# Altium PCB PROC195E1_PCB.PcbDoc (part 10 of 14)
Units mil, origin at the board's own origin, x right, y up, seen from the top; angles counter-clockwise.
Board outline 3110.24 x 2500 mil, 10 copper layers (Top Layer, L02_GND1, L03_SIG1, L04_GND2, L05_PWR1, L06_PWR2, L07_GND3, L08_SIG2, L09_GND4, Bottom Layer), stack 66.407 mil thick; 571 components, 538 nets, 6726 pads, 1286 vias.
Unrouted connection lines stored in the file: 4.
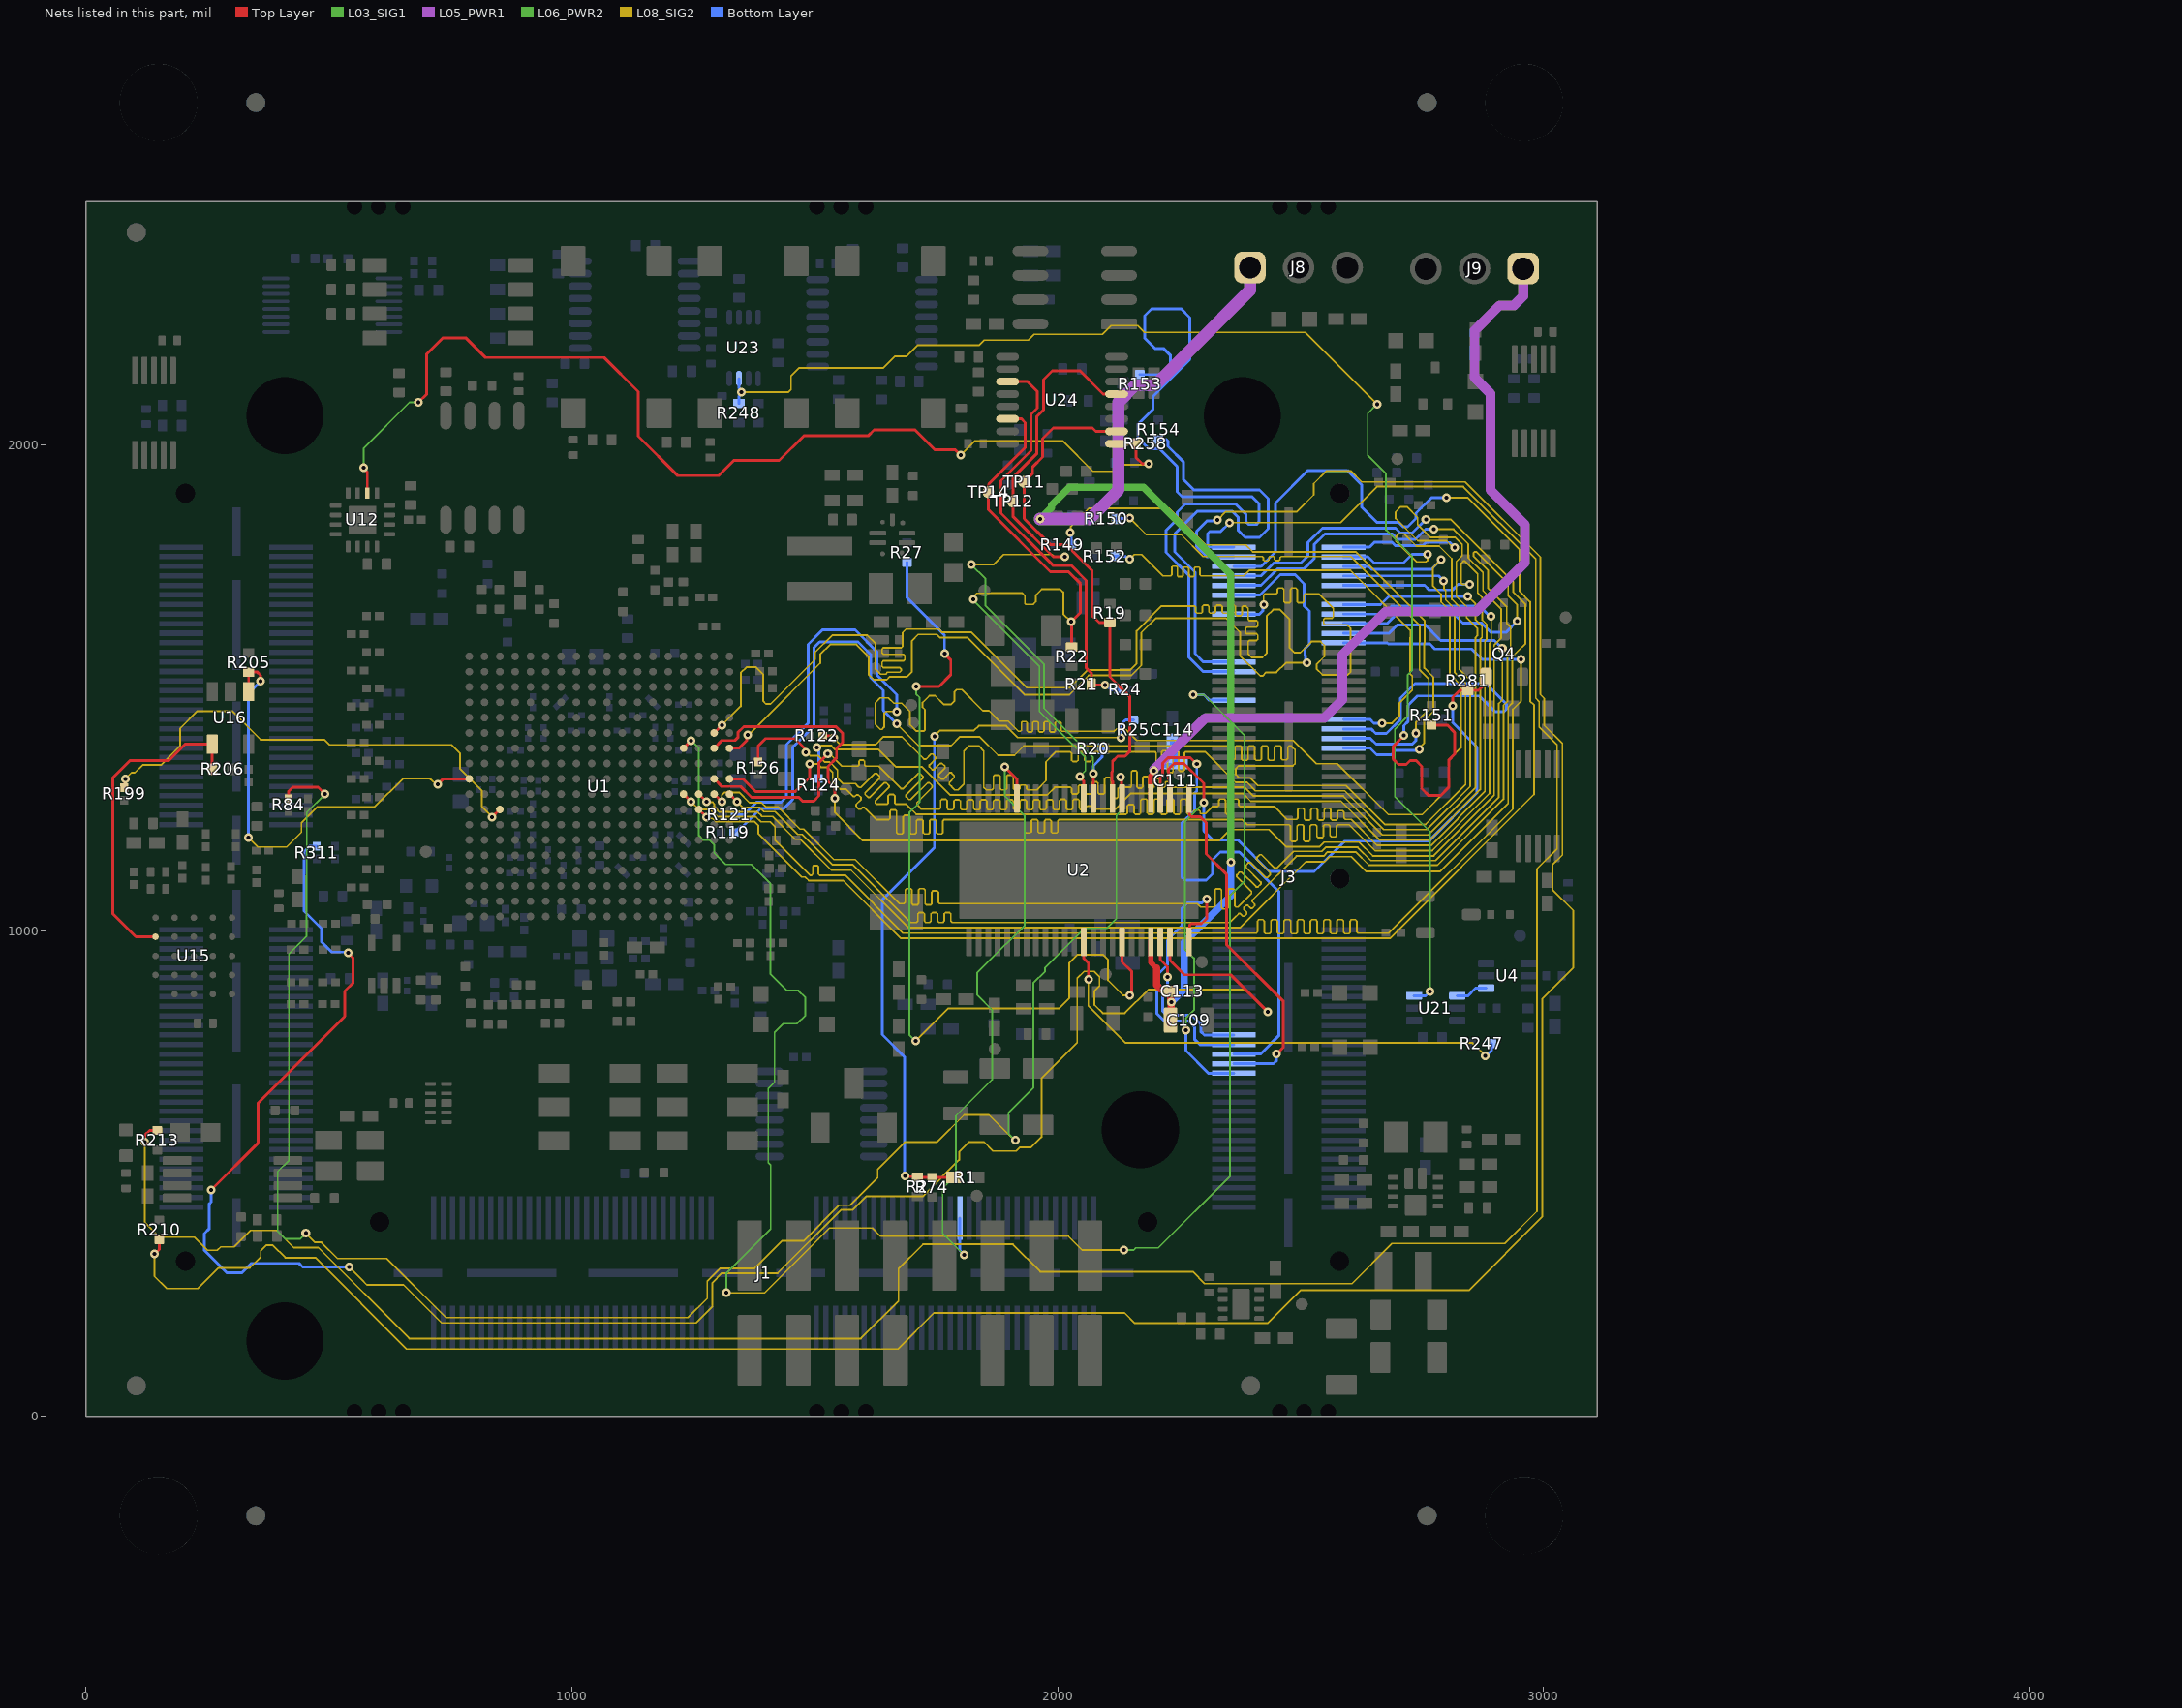
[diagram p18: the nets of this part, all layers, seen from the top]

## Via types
v1: diameter 18, hole 8, Top Layer to Bottom Layer, tented both sides, 1226 vias
v2: diameter 19.68, hole 7.87, Top Layer to Bottom Layer, tented top, 54 vias
v3: diameter 19.68, hole 7.87, Top Layer to Bottom Layer, 4 vias
v4: diameter 19.68, hole 7.87, Top Layer to Bottom Layer, tented both sides, 2 vias

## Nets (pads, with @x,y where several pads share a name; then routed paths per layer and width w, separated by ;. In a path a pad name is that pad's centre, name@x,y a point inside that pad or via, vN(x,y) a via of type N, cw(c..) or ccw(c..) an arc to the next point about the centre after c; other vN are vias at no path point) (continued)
OSPI0_LBCLK: R199.2 U1.L3 | length 1003.3
  Top Layer w5.8: R199.2@79.05,1294.4 80.37,1295.72 80.37,1311.13 v1(81.69,1312.45) ; v1(836.41,1233.76) U1.L3@852.13,1249.45
  L08_SIG2 w3.6: v1(81.69,1312.45) 94.26,1325.02 101.06,1325.02 116.84,1340.8 154.71,1340.8 194.27,1380.36 194.27,1416.24 229.73,1451.7 301,1451.7 359.61,1393.09 490.68,1393.09 501.3,1382.47 752.9,1382.47 770.02,1365.35 770.02,1333.28 815.33,1287.97 815.33,1254.84 v1(836.41,1233.76)
OSPI0_RESET_OUTn: R205.1 U1.J1 U16.1 | length 953.6
  Top Layer w5.8: U16.1@335.2,1491.94 R205.1@335.2,1531.94 353.14,1531.94 359.9,1525.19 359.9,1513.68 v1(360.01,1513.57) ; v1(724.08,1301.38) 724.68,1301.38 735.74,1312.44 771.03,1312.44 U1.J1@789.16,1312.44
  L08_SIG2 w3.6: v1(334.47,1191.98) 354.53,1171.92 413.48,1171.92 444,1202.44 444,1222 476.45,1254.45 594.28,1254.45 652.78,1312.96 707.98,1312.96 710.06,1310.88 711.04,1310.88 720.46,1301.46 720.54,1301.38 v1(724.08,1301.38)
  Bottom Layer w5.8: v1(334.47,1191.98) 334.47,1488.03 v1(360.01,1513.57)
OSPI0_RST#: R206.1 U15.A4 U16.4 | length 672.8
  Top Layer w5.8: U15.A4@143.59,987.35 103.2,987.35 55.36,1035.19 55.36,1314.09 91.59,1350.32 171.28,1350.32 204.64,1383.67 U16.4@260.39,1383.67 260.39,1333.05 R206.1@261.38,1332.07
PHY0_25MHZ_CLK: J3.117 R210.2 | length 5601
  Top Layer w5.8: v1(141.5,335) 142.36,335 151.15,343.78 R210.2@151.15,363.92
  L08_SIG2 w3.6: v1(141.5,335) 141.5,288.28 166.44,263.34 230.81,263.34 273.33,305.86 337.7,305.86 360.03,328.2 360.03,340.98 371.27,352.22 385.14,352.22 410.68,326.68 472.38,326.68 660.33,138.73 1265.59,138.73 1265.66,138.79 1671.15,138.79 1745.41,213.05 2137.55,213.05 2158.72,191.88 2431.91,191.88 2499.65,259.62 2846.1,259.62 2997.12,410.64 2997.12,859.28 3061.41,923.57 3061.41,1041.1 3018.06,1084.45 3018.06,1135.24 3038.5,1155.68 3038.5,1384.97 3001.35,1422.12 3001.35,1477.99 2993.41,1485.92 2993.41,1768.67 2838.78,1923.31 2625.69,1923.31 2603,1946 2553,1946 2527,1920 2527,1897 2492.43,1862.43 2346.49,1862.43 v1(2328.93,1844.87)
  Bottom Layer w5.8: v1(2328.93,1844.87) 2327.59,1843.54 2307.95,1843.54 2286.13,1821.72 2286.13,1790.02 2306.85,1769.31 J3.117@2362.43,1769.31
PHY1_25MHZ_CLK: J3.119 R213.2 | length 5655.9
  Top Layer w5.8: v1(121.78,564.83) 121.78,579.08 131.39,588.69 R213.2@147.24,588.69
  L08_SIG2 w3.6: v1(121.78,564.83) 121.78,398.63 151.57,368.84 223.72,368.84 250.64,341.92 270.88,341.92 277.91,348.96 305.01,348.96 339,382.95 392.57,382.95 427.96,347.57 478.64,347.57 665.88,160.33 1595.06,160.33 1672.55,237.82 1672.55,304 1722.88,354.34 1907.9,354.34 1964.27,297.97 2278.14,297.97 2302.66,273.44 2605.65,273.44 2688.32,356.12 2920.19,356.12 2986.32,422.25 2986.32,1126.89 3027.7,1168.26 3027.7,1382.2 2990.92,1418.97 2990.92,1471.38 2983.81,1478.48 2983.81,1764.69 2834.8,1913.71 2656.69,1913.71 2582.56,1839.58 v1(2353.36,1839.58)
  Bottom Layer w5.8: v1(2353.36,1839.58) 2353.36,1839.08 2335.33,1821.05 2312.92,1821.05 2309,1817.13 2309,1792.02 2311.87,1789.15 J3.119@2362.59,1789.15
PLDO1_OUT: C109.1 C113.1 J8.1 U2.20 | length 2391.8
  Top Layer w11: U2.20@2191.65,976.67 2191.65,934.71 2203.54,922.83
  Top Layer w15: 2203.54,922.82 2203.54,888.02 2212.33,879.23 2227.07,879.23 C113.1@2231.91,874.39 ; C109.1@2232.44,815.79 2233.27,816.63 2233.27,851.83 v1(2233.85,852.41) ; v1@2232.44,854.99 C113.1@2232.44,874.92
  L05_PWR1 w25: v1(1963.58,1847.2) 2065.28,1847.2 2125.34,1907.26 2125.34,2087.76 2160.58,2123 2201.16,2123 2278.66,2200.49 2278.66,2200.88 2395.83,2318.06 J8.1@2395.83,2364.93
  L06_PWR2 w15: v1(1963.58,1847.2) 1987.4,1871.01 1987.4,1875.32 2024.43,1912.35 2177.02,1912.35 2356.19,1733.17 v1(2356.19,1141.18)
  Bottom Layer w15: v1@2234.42,852.98 2260.24,878.8 2260.24,975.86 2356.19,1071.82 v1(2356.19,1141.18)
PLDO2_OUT: C111.1 C114.1 J9.1 U2.29 | length 1861.4
  Top Layer w10: U2.29@2191.65,1271.95 2191.65,1319.55 2195.1,1323 2195.1,1324.21 2198.24,1327.35 v1(2198.24,1329.51)
  L05_PWR1 w20: v1(2198.24,1329.51) 2198.24,1331.86 2304.44,1438.06 2549.06,1438.06 2586,1475 2586,1568 2675.07,1657.07 2861.31,1657.07 2961.89,1757.65 2961.89,1835.24 2890.27,1906.87 2890.27,2105.73 2858.11,2137.89 2858.11,2235.4 2909.68,2286.97 2939.05,2286.97 2957.95,2305.87 J9.1@2957.95,2362.59
  Bottom Layer w10: v1(2198.24,1329.51) 2198.46,1329.51 2208.96,1340.02 2236.25,1340.02 C111.1@2242.33,1346.1 ; C114.1@2235.75,1389.54 2235.75,1370.3 2241.61,1364.44 2241.61,1346.82 C111.1@2242.77,1345.66
PMIC_COMP1_IN+: J3.37 U2.21 | length 328.7
  Top Layer w5.8: U2.21@2211.34,976.67 2211.34,940.32 2226.05,925.6 v1@2226.05,904.23
  Bottom Layer w5.8: v1(2226.04,904.21) 2226.04,884.52 2215.95,874.43 2215.95,834.22 2223.93,826.24 2275.77,826.24 2295.15,806.86 2295.15,791.46 2301.51,785.1 J3.37@2362.59,785.1
PMIC_COMP1_IN-: J3.35 U2.24 | length 612.7
  Top Layer w5.8: U2.24@2270.39,976.67 2271.44,977.72 2271.44,1010.62 2274.84,1014.02 2296.1,1014.02 2306.7,1024.62 v1(2306.7,1065.31)
  Bottom Layer w5.8: v1(2306.7,1065.31) 2305.08,1065.31 2296.68,1056.91 2267.18,1056.91 2255.6,1045.33 2255.6,1009.89 2226.2,980.49 2226.2,929.68 2204.15,907.63 2204.15,829.33 2219.04,814.44 2269.19,814.44 2281.55,802.07 2281.55,776.56 2292.69,765.41 J3.35@2362.59,765.41
PMIC_COMP2_IN+: J3.33 U2.28 | length 1082.5
  Top Layer w5.8: U2.28@2211.34,1271.95 2210.87,1272.41 2210.87,1315.62 2216.14,1320.89 2216.14,1345.08 2226.85,1355.78 2273.13,1355.78 v1(2286.34,1342.57)
  Bottom Layer w5.8: v1(2286.34,1342.57) 2286.28,1342.51 2286.28,1287.3 2281.78,1282.8 2281.78,1247.14 2255.6,1220.96 2255.6,1110.46 2262.36,1103.7 2305.77,1103.7 2318.6,1116.53 2318.6,1145.81 2334.52,1161.73 2373.89,1161.73 2454.91,1080.71 2454.91,783.48 2417.16,745.73 J3.33@2362.59,745.73
PMIC_COMP2_IN-: J3.31 U2.25 | length 727.1
  Top Layer w5.8: U2.25@2270.39,1271.95 2271.44,1270.9 2271.44,1238 2274.84,1234.6 2293,1234.6 2293.39,1234.22 2293.46,1234.22 2305.65,1222.03 2305.65,1157.76 2347.28,1116.13 2347.28,971.51 2464.52,854.27 2464.52,760.21 v1(2450.71,746.4)
  Bottom Layer w5.8: J3.31@2362.59,726.04 2444.28,726.04 2450.71,732.48 v1(2450.71,746.4)
PMIC_DIAG_OUT: R84.2 U2.32 | length 3788.9
  Top Layer w5.8: R84.2@417.42,1271.47 417.42,1286.62 425.76,1294.97 478.38,1294.97 v1(492.49,1280.86) ; v1(2129.37,1316.27) 2130.98,1314.65 2130.98,1273.56 U2.32@2132.6,1271.95
  L03_SIG1 w3.6: v1(452.85,377.2) 440.84,365.19 411.04,365.19 395.11,381.12 395.11,504.05 417.84,526.78 417.84,952.31 454.6,989.07 454.6,1114.06 454.99,1114.46 454.99,1243.35 v1@492.49,1280.84 ; v1(1912.95,568.37) 1898.89,582.43 1898.89,625.05 1949.84,676.01 1949.84,891.8 1974.21,916.17 1974.21,923.65 2055.15,1004.6 2101.08,1004.6 2120.86,1024.38 2120.86,1062.66 2120.86,1236.86 2130.92,1246.92 2130.92,1314.71 v1(2129.37,1316.27)
  L08_SIG2 w3.6: v1(452.85,377.2) 471.69,358.37 484.99,358.37 518.09,325.27 619.57,325.27 741.32,203.53 1239.31,203.53 1278.75,242.96 1278.75,277.99 1305.23,304.47 1375.69,304.47 1432.62,361.39 1476.82,361.39 1550.14,434.72 1572.52,434.72 1629.48,491.69 1629.48,508.83 1685.25,564.59 1751.57,564.59 1807.54,620.55 1859.03,620.55 1911.22,568.37 v1(1912.95,568.37)
PMIC_EN_OUT: R27.1 U2.17 | length 1832.8
  Top Layer w5.8: v1(1708.6,1502.72) 1756.1,1502.72 1780.17,1526.79 1780.17,1556.82 v1(1767.22,1569.77) ; U2.17@2132.6,976.67 2132.6,935.67 2152.29,915.97 2152.29,874.06 2148.3,870.06 v1(2148.3,866.76)
  L03_SIG1 w3.6: v1(1707.74,772.84) 1694.78,785.81 1694.78,1243.13 1715.8,1264.15 1715.8,1479.7 1708.6,1486.9 v1(1708.6,1502.72)
  L08_SIG2 w3.6: v1(1707.74,772.84) 1774.9,840 2003.46,840 2023.61,860.15 2023.61,932.56 2041.61,950.56 2092.89,950.56 2103.72,939.73 2103.72,897.6 2134.55,866.76 v1(2148.3,866.76)
  Bottom Layer w5.8: R27.1@1689.83,1757.96 1689.83,1685.35 1767.22,1607.96 v1(1767.22,1569.77)
PMIC_INTn: R311.2 U2.22 | length 4209.8
  Top Layer w5.8: v1(257.93,466.28) 355.02,563.37 355.02,645.28 533.2,823.47 533.2,875.5 549.75,892.04 549.75,943.92 v1(539.62,954.06) ; U2.22@2231.02,976.67 2231.02,939.02 2261,909.04 2356.11,909.04 v1(2431.92,833.23)
  L08_SIG2 w3.6: v1(542.23,307.73) 542.23,307.38 567.49,282.13 578.77,270.84 654.16,270.84 732.27,192.73 1256.11,192.73 1289.55,226.16 1289.55,275.21 1309.2,294.87 1423.86,294.87 1554.12,425.12 1578.17,425.12 1605.91,452.86 1722,452.86 1797.33,528.18 1797.33,543.98 1818.23,564.88 1848.38,564.88 1866.9,546.36 1914.71,546.36 1922.27,553.92 1945.69,553.92 1966.74,574.97 1966.74,695.65 2040.3,769.21 2040.3,901.71 2054.68,916.09 2074.7,916.09 2085.94,904.84 2085.94,885.99 2075.75,875.8 2075.75,846.82 2092.65,829.92 2138.26,829.92 2186.79,878.45 2385.84,878.45 2431.07,833.23 v1(2431.92,833.23)
  Bottom Layer w5.8: v1(257.93,466.28) 257.93,441.29 254.41,437.76 254.41,386.74 243.88,376.22 243.88,342.06 289.86,296.09 321.84,296.09 340.88,315.13 438.7,315.13 446.27,307.56 542.06,307.56 v1(542.23,307.73) ; R311.2@475.11,1173.35 460.32,1173.35 449.51,1162.54 449.51,1040.13 485.39,1004.25 485.39,976.78 506.31,955.85 537.82,955.85 v1(539.62,954.06)
PMIC_nRST: R247.1 U2.13 | length 1026.1
  Top Layer w5.8: U2.13@2053.86,976.67 2053.86,942.99 2063.21,933.64 v1(2063.21,899.29)
  L08_SIG2 w3.6: v1(2063.21,899.29) 2063.21,845.64 2140.04,768.81 2853.65,768.81 v1(2880.16,742.3)
  Bottom Layer w5.8: v1(2880.16,742.3) 2881.81,742.3 2892.88,753.37 R247.1@2892.88,767.51
PMIC_SAFE_OUT1: R1.1 R2.2 R25.2 R74.2 | length 1529.6
  Top Layer w5.8: v1(1685.66,495) 1687.19,493.47 1709.94,493.47 R2.2@1711.47,491.94 R74.2@1741.47,491.94 R1.1@1786.47,491.94
  L08_SIG2 w3.6: v1(1747.18,1399.72) 1747.18,1400.58 1758.55,1411.96 1828.1,1411.96 1837.7,1421.55 1893.98,1421.55 1905.87,1409.66 1918.04,1397.49 v1@2129.79,1397.49
  Bottom Layer w5.8: v1(1685.66,495) 1685.21,495.46 1685.21,739.6 1638.91,785.9 1638.91,1063.47 1746.29,1170.86 1746.29,1398.84 v1(1747.18,1399.72) ; v1(2130.05,1397.24) 2130.05,1423.7 2139.99,1433.64 R25.2@2155.94,1433.64
PMIC_SAFE_OUT2: J3.29 Q4.1 R281.2 U2.27 | length 1888
  Top Layer w5.8: U2.27@2231.17,1272.09 2231.17,1309.08 2227.94,1312.3 2227.94,1332.41 2239.51,1343.98 2259.62,1343.98 2300.5,1303.1 v1(2300.5,1263.04) ; v1(2812.9,1462.61) 2812.9,1480.31 2826.71,1494.11 2843.59,1494.11 R281.2@2843.82,1494.34 2866.04,1494.34 2874.43,1502.74 2874.43,1515.05 Q4.1@2881.49,1522.1
  L03_SIG1 w3.6: v1(2263.65,794.66) 2264.04,795.05 2264.04,820.03 2280.72,836.71 2280.72,943.22 2261.74,962.2 2261.74,1224.28 v1(2300.5,1263.04)
  Bottom Layer w5.8: v1(2263.65,794.66) 2263.65,753.04 2310.33,706.36 J3.29@2362.59,706.36 ; v1(2300.5,1263.04) 2300.5,1205.15 2319.37,1186.27 2370.94,1186.27 2435.56,1121.66 2528.18,1121.66 2590.52,1184 2763.59,1184 2863,1283.41 2863,1378 2812.9,1428.1 v1(2812.9,1462.61)
PMIC_SPI1/FSIRX0_MUX_SEL: R258.1 U12.2 U24.1 | length 2228.7
  Top Layer w5.8: v1(572.15,1952.84) 572.15,1951.11 579.39,1943.87 U12.2@579.39,1900.61 ; v1(684.78,2087.42) 701.25,2103.9 701.25,2186.66 734.12,2219.54 782.78,2219.54 822.72,2179.6 1066.75,2179.6 1136.93,2109.43 1136.93,2017.51 1218,1936.44 1302.45,1936.44 1333.73,1967.72 1427.07,1967.72 1477.61,2018.25 1609.91,2018.25 1622.36,2030.7 1706.46,2030.7 1747.84,1989.32 1789.8,1989.32 v1(1800.48,1978.63) ; U24.1@2121.29,2002.06 R258.1@2161.29,2002.06 2161.29,1973.44 2173.96,1960.77 v1(2187.23,1960.77)
  L03_SIG1 w3.6: v1(572.15,1952.84) 572.15,1993.18 666.4,2087.42 v1(684.78,2087.42)
  L08_SIG2 w3.6: v1(1800.48,1978.63) 1829.65,2007.8 2010.19,2007.8 2072.61,1945.39 2120.82,1945.39 2134.37,1958.94 2185.4,1958.94 v1(2187.23,1960.77)
PMIC_SPI1_CLK: R19.2 TP11.1 U2.33 U24.2 | length 1066.7
  Top Layer w5.8: TP11.1@1931.18,1923.68 1931.2,1847.84 1984.32,1794.72 2016.86,1794.72 2071.13,1740.46 2071.13,1648.62 2085.58,1634.17 2107,1634.17 R19.2@2107.45,1633.72 2107.45,1522.58 2147.95,1482.09 2147.95,1368.39 2138.73,1359.17 2123.51,1359.17 2113.02,1348.68 2113.02,1327.92 2111.47,1326.37 2111.47,1308.85 2113.1,1307.22 U2.33@2113.1,1272.13 ; TP11.1@1931.18,1923.68 1948.48,1940.98 1948.48,1954.5 1968.94,1974.96 1968.94,2012.7 1991,2034.76 2071.42,2034.76 2078.53,2027.65 U24.2@2121.3,2027.65
PMIC_SPI1_CS0: R22.2 TP14.1 U2.36 U24.14 | length 1458.6
  Top Layer w5.8: TP14.1@1857.69,1902.47 1857.67,1866.22 1985.01,1738.88 2022.21,1738.88 2047,1714.09 2047,1654.93 2028.5,1636.43 v1@2028.5,1635.86 ; TP14.1@1857.69,1902.47 1858.12,1902.9 1858.12,1919.3 1933.05,1994.23 1933.05,2045.72 1925.54,2053.24 U24.14@1896.89,2053.24 ; v1(2028.21,1636.14) 2028.96,1635.4 R22.2@2028.96,1583.68 ; v1(2045.5,1317.37) 2045.5,1316.12 2053.86,1307.75 U2.36@2053.86,1271.95
  L03_SIG1 w3.6: v1(1826.19,1682.21) 1826.19,1680.26 1962.5,1543.95 1962.5,1450.94 2057.19,1356.25 2057.19,1329.06 v1(2045.5,1317.37)
  L08_SIG2 w3.6: v1(1826.19,1682.21) 1826.19,1686.11 1830.44,1690.37 1830.44,1691.12 1833.46,1694.13 1862.95,1694.13 1863.38,1694.56 1911.84,1694.56 1912.26,1694.98 1926.42,1694.98 1932.64,1688.76 1932.64,1673.67 1934.87,1671.45 1949.45,1671.45 1955,1677 1955,1690.52 1967.25,1702.77 2005.31,1702.77 2011.59,1696.5 2011.59,1651.71 2027.16,1636.14 v1(2028.21,1636.14)
PMIC_SPI1_D0: R20.2 TP12.1 U2.35 U24.5 | length 1474.7
  Top Layer w5.8: v1(2015.17,1769.78) 1990.88,1769.78 1907.87,1852.78 TP12.1@1907.87,1883.27 1907.87,1932.28 1956.65,1981.06 1956.65,2057.54 1971,2071.89 1971,2134 1989,2152 2046.35,2152 2093.82,2104.53 U24.5@2121.18,2104.53 ; U2.35@2073.54,1271.95 v1@2073.54,1322.83
  L03_SIG1 w3.6: v1(1822.07,1753.36) 1851.58,1723.84 1851.58,1668.45 1972.1,1547.92 1972.1,1457.26 2073.28,1356.08 v1@2073.28,1322.98
  L08_SIG2 w3.6: v1(1822.07,1753.36) 1868.06,1753.36 1888.8,1774.1 1988.22,1774.1 1992.54,1769.78 v1(2015.17,1769.78)
  Bottom Layer w5.8: v1(2073.39,1322.98) 2073.39,1339.17 2091.58,1357.36 2091.58,1373.28 R20.2@2092.77,1374.47
PMIC_SPI1_D1: R21.2 R24.1 U24.11 | length 862
  Top Layer w5.8: U24.11@1896.89,2130.01 1937.65,2130.01 1957.9,2109.76 1957.9,2075.47 1944.85,2062.43 1944.85,1987.64 1883.29,1926.08 1883.29,1858.98 1990.39,1751.88 2027.6,1751.88 2058.8,1720.68 2058.8,1540.86 2069.21,1530.45 R21.2@2069.21,1507.27 ; R21.2@2069.8,1506.68 2071.33,1505.15 v1(2097.43,1505.15)
  Bottom Layer w5.8: v1(2097.43,1505.15) 2100.54,1505.15 2109.94,1495.75 R24.1@2125.65,1495.75
PMIC_WAKE2: J1.30 U2.43 | length 1290.7
  Top Layer w5.8: v1(1891.04,1336.59) 1916.06,1311.56 U2.43@1916.06,1271.95
  L03_SIG1 w3.6: v1(1807.47,332.34) 1763.04,376.77 1763.04,469.46 1790.54,496.96 1790.54,618.66 1865.25,693.37 1865.25,836.76 1834.66,867.34 1834.66,913.7 1893.97,973 1895,973 1932.35,1010.35 1932.35,1029.93 1931.89,1030.39 1931.89,1174.92 1932.35,1175.39 1932.35,1236.29 1891.04,1277.6 v1(1891.04,1336.59)
  Bottom Layer w5.8: J1.30@1798.64,408.19 1798.64,341.84 1807.47,333.01 v1(1807.47,332.34)
PORz_RST: R248.2 U21.3 U23.7 | length 2839.8
  L03_SIG1 w3.6: v1(2657.1,2083.61) 2638,2064.5 2638,1978.25 2675.69,1940.56 2675.69,1824.57 2729.21,1771.04 2729.21,1535.21 2720.23,1526.23 2720.23,1440.96 2693.88,1414.62 2693.88,1276.13 2766.52,1203.5 v1(2766.52,874.98)
  L08_SIG2 w3.6: v1(1348.92,2108.29) 1349.17,2108.05 1445.56,2108.05 1451.12,2113.61 1451.12,2141.46 1467.62,2157.97 1640.68,2157.97 1664.48,2181.77 1688.65,2181.77 1711.69,2204.82 1837.97,2204.82 1848.67,2215.52 1939.5,2215.52 1951.3,2227.31 2091.72,2227.31 2109.66,2245.26 2164.67,2245.26 2178.46,2231.47 2509.24,2231.47 v1(2657.1,2083.61)
  Bottom Layer w5.8: R248.2@1344.16,2084.95 1344.16,2100.22 1348.92,2104.99 v1(1348.92,2108.29) ; U23.7@1344.16,2136.43 1344.16,2116.35 1348.43,2112.09 v1@1348.43,2107.79 ; U21.3@2733.62,865.86 2757.39,865.86 v1(2766.52,874.98)
PORz_VMAIN: U4.1 U21.4 | length 66.2
  Bottom Layer w5.8: U21.4@2822.2,865.86 2844.54,865.86 2860.05,881.37 U4.1@2881.98,881.37
PR0_PRU0_GPIO0: J3.102 U1.K17 | length 3093.5
  Top Layer w5.8: U1.K17@1293.1,1280.94 v1(1308.85,1265.19)
  L08_SIG2 w3.6: v1@1308.67,1264.8 1308.67,1278.5 1314.5,1284.32 1345.06,1284.32 1366.02,1263.36 1390.29,1263.36 1390.65,1263.36 1399.48,1254.53 1424.11,1254.53 1469.72,1208.92 1476.88,1208.92 1539.49,1146.31 1583.35,1146.31 1674.1,1055.56 1681.99,1055.56 1683.79,1055.56 1686.51,1058.28 1686.51,1083.72 1689.23,1086.44 1697.39,1086.44 1700.11,1083.72 1700.11,1055.47 1702.83,1052.75 1710.99,1052.75 1713.71,1055.47 1713.71,1083.72 1716.43,1086.44 1724.59,1086.44 1727.31,1083.72 1727.31,1055.47 1730.03,1052.75 1738.19,1052.75 1740.91,1055.47 1740.91,1079.43 1743.63,1082.15 1751.79,1082.15 1754.51,1079.43 1754.51,1058.28 1757.23,1055.56 1777.78,1055.56 2287.33,1055.56 2294.38,1048.51 2318.98,1048.51 2320.78,1048.51 2323.5,1051.23 2323.5,1083.4 2326.22,1086.12 2334.38,1086.12 2337.1,1083.4 2337.1,1047.27 2339.82,1044.55 2347.98,1044.55 2350.7,1047.27 2350.7,1083.4 2353.42,1086.12 2361.58,1086.12 2364.3,1083.4 2364.3,1051.23 2367.02,1048.51 2370.96,1048.51 2379.7,1057.25 2397.72,1075.26 2398.99,1076.53 2398.99,1080.38 2368.63,1110.74 2368.63,1114.59 2374.4,1120.36 2378.25,1120.36 2408.61,1090 2412.45,1090 2418.22,1095.77 2418.22,1099.61 2387.52,1130.31 2387.52,1134.16 2393.29,1139.93 2397.14,1139.93 2427.84,1109.23 2431.69,1109.23 2437.46,1115 2437.46,1118.85 2409.71,1146.6 2409.71,1150.44 2415.48,1156.21 2419.32,1156.21 2447.07,1128.46 2450.92,1128.46 2456.42,1133.97 2485.64,1163.18 2543.51,1163.18 2551.72,1171.39 2617.49,1171.39 2644.58,1144.3 2777.79,1144.3 2907.9,1274.41 2907.9,1467.5 2915.1,1474.7 v1(2915.1,1580.73)
  Bottom Layer w5.8: J3.102@2588.19,1611.99 2681.92,1611.99 2698.72,1628.79 2756.6,1628.79 2788.02,1597.36 2898.46,1597.36 v1(2915.1,1580.73)
PR0_PRU0_GPIO1: J3.104 U1.K18 | length 3091.2
  Top Layer w5.8: U1.K18@1324.6,1280.94 v1(1340.34,1265.19)
  L08_SIG2 w3.6: v1(1340.34,1265.19) 1351.78,1253.76 1386.67,1253.76 1390.29,1250.14 1395.5,1244.93 1418.32,1244.93 1465.14,1198.12 1474.11,1198.12 1536.72,1135.51 1578.88,1135.51 1697.61,1016.78 1707.66,1016.78 ; 1707.68,1016.78 1709.48,1016.78 1712.2,1019.5 1712.2,1034.29 1714.92,1037.01 1723.08,1037.01 1725.8,1034.29 1725.8,1019.5 1728.52,1016.78 1736.68,1016.78 1739.4,1019.5 1739.4,1034.29 1742.12,1037.01 1750.28,1037.01 1753,1034.29 1753,1019.5 1755.72,1016.78 1763.88,1016.78 1766.6,1019.5 1766.6,1034.29 1769.32,1037.01 1777.48,1037.01 1780.2,1034.29 1780.2,1019.5 1782.92,1016.78 1786,1016.78 2354.51,1016.78 2363.07,1025.34 2372.54,1034.81 2375.82,1034.81 2380.88,1029.76 2384.16,1029.76 2389.08,1034.68 2389.08,1037.96 2383.18,1043.86 2383.18,1047.14 2388.1,1052.07 2391.38,1052.07 2397.28,1046.16 2400.56,1046.16 2405.48,1051.08 2405.48,1054.36 2400.43,1059.42 2400.43,1062.7 2410.72,1073 2491.31,1153.58 2547.49,1153.58 2555.7,1161.79 2613.51,1161.79 2640.6,1134.7 2781.77,1134.7 2917.5,1270.43 2917.5,1463.52 2925.7,1471.73 2925.7,1567.57 2927.11,1568.98 2931.9,1573.77 2931.9,1624.3 2924,1632.2 2924,1666.21 2885.99,1704.22 2885.99,1741.01 2855.62,1771.38 2855.62,1776.68 2858.63,1779.69 2861.62,1779.69 2926.91,1714.39 2926.91,1689.08 2945.72,1670.27 v1(2945.72,1636.85)
  Bottom Layer w5.8: J3.104@2588.19,1631.67 2677.75,1631.67 2698.99,1652.91 2814.26,1652.91 2834.01,1633.16 2872.3,1633.16 2891.15,1614.31 2923.18,1614.31 v1(2945.72,1636.85)
PR0_PRU0_GPIO2: J3.106 U1.J18 | length 3092.3
  Top Layer w5.8: U1.J18@1324.6,1312.44 1352.21,1312.44 1378.53,1286.12 1390.29,1286.12 1460.38,1286.12 1489.54,1315.28 v1(1489.54,1343.3)
  L08_SIG2 w3.6: v1(1489.54,1343.3) 1505.86,1343.3 1512.88,1336.28 1526.08,1336.28 1536.83,1325.53 1536.83,1306.99 1552.37,1291.45 1563.93,1291.45 1577.79,1277.6 1579.06,1276.32 1582.91,1276.32 1585.76,1279.17 1589.61,1279.17 1595.38,1273.4 1595.38,1269.56 1585.37,1259.55 1585.37,1255.7 1591.14,1249.93 1594.99,1249.93 1598.3,1253.24 1602.14,1253.24 1603.53,1251.86 1604.8,1250.59 1626.82,1228.57 1650.56,1228.57 1652.36,1228.57 1655.08,1231.29 1655.08,1245.79 1657.8,1248.51 1665.96,1248.51 1668.68,1245.79 1668.68,1201.67 1671.4,1198.95 1679.56,1198.95 1682.28,1201.67 1682.28,1234.53 1685,1237.25 1693.16,1237.25 1695.88,1234.53 1695.88,1201.67 1698.6,1198.95 1706.76,1198.95 1709.48,1201.67 1709.48,1225.85 1712.2,1228.57 1720.36,1228.57 1723.08,1225.85 1723.08,1201.67 1725.8,1198.95 1733.96,1198.95 1736.68,1201.67 1736.68,1225.85 1739.4,1228.57 1747.56,1228.57 1750.28,1225.85 1750.28,1201.67 1753,1198.95 1761.16,1198.95 1763.88,1201.67 1763.88,1225.85 1766.6,1228.57 1792.73,1228.57 1914.12,1228.57 1929.52,1228.57 1932.24,1225.85 1932.24,1203.57 1934.96,1200.85 1943.12,1200.85 1945.84,1203.57 1945.84,1225.85 1948.56,1228.57 1956.72,1228.57 1959.44,1225.85 1959.44,1203.57 1962.16,1200.85 1970.32,1200.85 1973.04,1203.57 1973.04,1225.85 1975.76,1228.57 1983.92,1228.57 1986.64,1225.85 1986.64,1203.57 1989.36,1200.85 1997.52,1200.85 2000.24,1203.57 2000.24,1225.85 2002.96,1228.57 2025.29,1228.57 2379.37,1228.57 2389.89,1218.05 2460.76,1218.05 2476.16,1218.05 2478.88,1215.33 2478.88,1186.3 2481.6,1183.58 2489.76,1183.58 2492.48,1186.3 2492.48,1215.33 2495.2,1218.05 2503.36,1218.05 2506.08,1215.33 2506.08,1186.3 2508.8,1183.58 2516.96,1183.58 2519.68,1186.3 2519.68,1215.33 2522.4,1218.05 2530.56,1218.05 2533.28,1215.33 2533.28,1193.96 2536,1191.24 2544.16,1191.24 2546.88,1193.96 2546.88,1215.33 2549.6,1218.05 2557.76,1218.05 2560.48,1215.33 2560.48,1195.67 2563.2,1192.95 2571.36,1192.95 2574.08,1195.67 2574.08,1215.33 2576.8,1218.05 2592.11,1218.05 2599.68,1218.05 2653.03,1164.7 2771.04,1164.7 2888.7,1282.36 2888.7,1591.66 2892.35,1595.31 2892.35,1646.08 v1(2891.36,1647.06)
  Bottom Layer w5.8: J3.106@2588.19,1651.36 2671.38,1651.36 2687.62,1667.6 2868.7,1667.6 2889.23,1647.06 v1(2891.36,1647.06)
PR0_PRU0_GPIO3: J3.108 U1.J17 | length 3095.7
  Top Layer w5.66: 1308.85,1296.69 1339.11,1296.69
  Top Layer w5.8: U1.J17@1293.1,1312.44 1308.85,1296.69 ; 1339.11,1296.69 1347.77,1296.69 1370.14,1274.32 1467.28,1274.32 1475,1266.59 1498.41,1266.59 1508.77,1276.95 1508.77,1345.64 v1(1527.01,1363.88)
  L08_SIG2 w3.6: v1(1527.01,1363.88) 1530.68,1363.88 1556,1338.56 1586.92,1338.56 1588.72,1338.56 1591.04,1340.88 1591.04,1348.59 1593.36,1350.91 1600.32,1350.91 1602.64,1348.59 1602.64,1340.88 1604.96,1338.56 1612.9,1338.56 1631.31,1338.56 1676.52,1293.35 1677.8,1292.07 1681.64,1292.07 1712.97,1323.41 1716.82,1323.41 1722.59,1317.64 1722.59,1313.79 1688.16,1279.36 1688.16,1275.51 1693.93,1269.74 1697.78,1269.74 1732.21,1304.17 1736.05,1304.17 1741.82,1298.4 1741.82,1294.56 1710.49,1263.22 1710.49,1259.38 1713.16,1256.71 1714.44,1255.44 1719.7,1250.17 1754.6,1250.17 1756.4,1250.17 1759.12,1252.89 1759.12,1267.45 1761.84,1270.17 1770.01,1270.17 1772.72,1267.45 1772.72,1251.69 1775.44,1248.97 1783.61,1248.97 1786.32,1251.69 1786.32,1266.61 1789.05,1269.33 1797.2,1269.33 1799.92,1266.61 1799.92,1251.69 1802.64,1248.97 1810.8,1248.97 1813.53,1251.69 1813.53,1266.61 1816.24,1269.33 1824.4,1269.33 1827.12,1266.61 1827.12,1251.69 1829.84,1248.97 1838.01,1248.97 1840.72,1251.69 1840.72,1266.61 1843.44,1269.33 1851.61,1269.33 1854.32,1266.61 1854.32,1251.69 1857.05,1248.97 1865.2,1248.97 1867.92,1251.69 1867.92,1266.61 1870.64,1269.33 1878.8,1269.33 1881.53,1266.61 1881.53,1251.69 1884.24,1248.97 1892.4,1248.97 1895.12,1251.69 1895.12,1266.61 1897.84,1269.33 1906.01,1269.33 1908.72,1266.61 1908.72,1251.69 1911.44,1248.97 1919.61,1248.97 1922.32,1251.69 1922.32,1266.61 1925.05,1269.33 1933.2,1269.33 1935.92,1266.61 1935.92,1251.69 1938.64,1248.97 1946.8,1248.97 1949.53,1251.69 1949.53,1266.61 1952.24,1269.33 1960.4,1269.33 1963.12,1266.61 1963.12,1251.69 1965.84,1248.97 1974.01,1248.97 1976.72,1251.69 1976.72,1266.61 1979.44,1269.33 1987.61,1269.33 1990.32,1266.61 1990.32,1251.69 1993.05,1248.97 2001.2,1248.97 2003.92,1251.69 2003.92,1267.45 2006.64,1270.17 2014.8,1270.17 2017.53,1267.45 2017.53,1251.69 2020.24,1248.97 2028.4,1248.97 2031.12,1251.69 2031.12,1267.45 2033.84,1270.17 2042.01,1270.17 2044.72,1267.45 2044.72,1251.69 2047.44,1248.97 2055.61,1248.97 2058.32,1251.69 2058.32,1253.31 2061.05,1256.03 2069.2,1256.03 2071.92,1253.31 2071.92,1252.89 2074.64,1250.17 2114.57,1250.17 2118.94,1250.17 2151.17,1282.4 2381.3,1282.4 2397.5,1266.2 2583.24,1266.2 2663.14,1186.3 2765.49,1186.3 2869.5,1290.31 2869.5,1599.61 2873.15,1603.26 2873.15,1626.2 2860.07,1639.27 2860.07,1672 v1(2844.24,1687.83)
  Bottom Layer w5.8: J3.108@2588.19,1671.04 2664.63,1671.04 2681.42,1687.83 v1(2844.24,1687.83)
PR0_PRU0_GPIO4: J3.113 U1.K16 | length 3095.8
  Top Layer w5.8: U1.K16@1261.61,1280.94 v1(1277.35,1265.19)
  L08_SIG2 w3.6: v1(1277.35,1265.19) 1278.11,1264.43 1289.64,1264.43 1293.25,1260.83 1293.25,1255.03 1304.12,1244.16 1382.7,1244.16 1390.29,1236.57 1391.89,1234.96 1413.02,1234.96 1459.77,1188.21 1470.44,1188.21 1533.94,1124.71 1574.4,1124.71 1693.13,1005.98 2374.81,1005.98 2510.52,1141.69 2549.17,1141.69 2559.68,1152.19 2604.45,1152.19 2635.14,1121.5 2786.51,1121.5 2927.1,1262.09 2927.1,1459.55 2935.3,1467.76 2935.3,1563.6 2936.71,1565.01 2946.55,1574.85 2962.72,1591.01 2962.72,1671.09 2937.71,1696.09 2937.71,1717.17 2808.37,1846.51 v1(2757.7,1846.51)
  Bottom Layer w5.8: J3.113@2362.59,1730.1 2418.35,1730.1 2444.61,1756.36 2500.27,1756.36 2514.64,1770.73 2514.64,1798.16 2544.76,1828.28 2695.4,1828.28 2705.49,1818.19 2729.39,1818.19 v1(2757.7,1846.51)
PR0_PRU0_GPIO5: J3.111 U1.G17 | length 3067.3
  Top Layer w5.6: U1.G17@1293.1,1375.43 1308.89,1391.22
  Top Layer w5.66: 1308.89,1391.22 1335.64,1391.22 1341.82,1397.39
  Top Layer w5.8: 1341.82,1397.39 1341.82,1407.51 1353.93,1419.62 1390.29,1419.62 1544.01,1419.62 1557.05,1406.57 1557.05,1386.83 1544.91,1374.69 1544.91,1355.32 1527.48,1337.89 1527.48,1306.94 1541.67,1292.76 v1(1541.67,1272.47)
  L08_SIG2 w3.6: v1(1541.67,1272.47) 1541.67,1242.75 1599.15,1185.26 2051.32,1185.26 2332.12,1185.26 2354.88,1208.02 2434.53,1208.02 2469.77,1172.78 2539.54,1172.78 2548.67,1181.91 2620.55,1181.91 2648.56,1153.9 2773.82,1153.9 2898.3,1278.38 2898.3,1587.68 2912.37,1601.76 2912.37,1662.56 2875.19,1699.74 2875.19,1736.72 2844.82,1767.08 2844.82,1795.98 2814.79,1826.01 v1(2774.48,1826.01)
  Bottom Layer w5.8: J3.111@2362.59,1710.41 2418.25,1710.41 2452.03,1744.2 2506.49,1744.2 2527.64,1765.35 2527.64,1794.48 2549.64,1816.48 2688.82,1816.48 2700.1,1805.19 2736.28,1805.19 2757.09,1826.01 v1(2774.48,1826.01)
PR0_PRU0_GPIO6: J3.100 U1.K15 | length 3084.4
  Top Layer w5.8: U1.K15@1230.11,1280.94 v1(1245.86,1265.19)
  L08_SIG2 w3.6: v1(1245.86,1265.19) 1261.65,1249.4 1285.3,1249.4 1300.42,1234.28 1379,1234.28 1389.26,1224.01 1408.69,1224.01 1418.53,1214.17 1418.53,1185.88 1490.5,1113.91 1491.89,1113.91 1493.69,1113.91 1496.01,1116.23 1496.01,1131.59 1498.33,1133.91 1505.29,1133.91 1507.61,1131.59 1507.61,1116.23 1509.93,1113.91 1531.9,1113.91 1562.85,1113.91 1681.87,994.88 2406.95,994.88 2408.75,994.88 2411.47,997.6 2411.47,1019.81 2414.19,1022.53 2422.35,1022.53 2425.07,1019.81 2425.07,996.4 2427.79,993.68 2435.95,993.68 2438.67,996.4 2438.67,1019.81 2441.39,1022.53 2449.55,1022.53 2452.27,1019.81 2452.27,996.4 2454.99,993.68 2463.15,993.68 2465.87,996.4 2465.87,1019.81 2468.59,1022.53 2476.75,1022.53 2479.47,1019.81 2479.47,996.4 2482.19,993.68 2490.35,993.68 2493.07,996.4 2493.07,1019.81 2495.79,1022.53 2503.95,1022.53 2506.67,1019.81 2506.67,996.4 2509.39,993.68 2517.55,993.68 2520.27,996.4 2520.27,1019.81 2522.99,1022.53 2531.15,1022.53 2533.87,1019.81 2533.87,996.4 2536.59,993.68 2544.75,993.68 2547.47,996.4 2547.47,1019.81 2550.19,1022.53 2558.35,1022.53 2561.07,1019.81 2561.07,996.4 2563.79,993.68 2571.95,993.68 2574.67,996.4 2574.67,1019.81 2577.39,1022.53 2585.55,1022.53 2588.27,1019.81 2588.27,996.4 2590.99,993.68 2599.15,993.68 2601.87,996.4 2601.87,1019.81 2604.59,1022.53 2612.75,1022.53 2615.47,1019.81 2615.47,997.6 2618.19,994.88 2645.92,994.88 2681.22,994.88 2936.7,1250.36 2936.7,1455.57 2953.51,1472.39 v1(2953.51,1558.05)
  Bottom Layer w5.8: J3.100@2588.19,1592.3 2678.29,1592.3 2680.68,1589.91 2766.15,1589.91 2776.39,1579.68 2852.11,1579.68 2873.74,1558.05 v1(2953.51,1558.05)
PR0_PRU0_GPIO8: J3.87 U1.G15 | length 3716.3
  Top Layer w5.8: U1.G15@1230.11,1375.43 v1(1245.86,1391.18)
  L03_SIG1 w3.6: v1(1245.86,1391.18) 1261.56,1375.48 1261.56,1227.19 1261.56,1195.79 1270.9,1186.45 1283.81,1186.45 1293.05,1177.21 1293.05,1160.48 1317.11,1136.42 1345.92,1136.42 1369.38,1136.42 1408.78,1097.02 1408.78,911.22 1443.51,876.48 1466.49,876.48 1480.77,862.2 1480.77,825.72 1463.6,808.55 1435.59,808.55 1417.31,790.27 1417.31,688.22 1404.36,675.27 1404.36,522.48 1409.28,517.57 1409.28,386.14 1318.54,295.4 v1(1318.54,254.39) ; v1(2136.53,342.55) 2156.4,342.55 2160.89,347.04 2207.17,347.04 2354.85,494.72 2354.85,1072.13 2383.99,1101.27 2383.99,1402.45 2300.77,1485.67 v1(2279.18,1485.67)
  L08_SIG2 w3.6: v1(1318.54,254.39) 1396.96,254.39 1530.45,387.87 1618.46,387.87 1634.83,371.5 2021.5,371.5 2050.45,342.55 v1(2136.53,342.55)
  Bottom Layer w5.8: v1(2279.18,1485.67) 2300.66,1485.67 2312.14,1474.19 J3.87@2362.59,1474.19
PR0_PRU0_GPIO9: J3.105 U1.F17 | length 3098.9
  Top Layer w5.8: U1.F17@1293.1,1406.93 v1(1308.85,1422.67)
  L08_SIG2 w3.6: v1(1308.85,1422.67) 1348,1461.82 1348,1530.62 1359.6,1542.22 1379.33,1542.22 1390.29,1531.26 1394.15,1527.4 1394.15,1472.04 1399.59,1466.6 1409.55,1466.6 1500.69,1557.74 1500.69,1572.47 1536.21,1607.99 1608.29,1607.99 1625,1591.28 1625,1539 1636,1528 1646.27,1528 1649.94,1531.67 1674.67,1531.67 1676,1533 1677.8,1534.8 1677.8,1538.65 1675.08,1541.37 1641.28,1541.37 1638.56,1544.09 1638.56,1552.25 1641.28,1554.97 1682.59,1554.97 1685.31,1557.69 1685.31,1565.85 1682.59,1568.57 1641.28,1568.57 1638.56,1571.29 1638.56,1579.45 1641.28,1582.17 1678.28,1582.17 1681,1584.89 1681,1594.17 1681,1613.5 1687.91,1620.41 1755.8,1620.41 1762.42,1613.79 1822.87,1613.79 1936.67,1499.99 2024.77,1499.99 2060.95,1536.17 2148.8,1536.17 2162.36,1549.73 2162.36,1616.86 2213.55,1668.05 2266.02,1668.05 2281.42,1668.05 2284.14,1665.33 2284.14,1655.93 2286.86,1653.21 2295.02,1653.21 2297.74,1655.93 2297.74,1667.1 2300.46,1669.82 2308.62,1669.82 2311.34,1667.1 2311.34,1655.93 2314.06,1653.21 2322.22,1653.21 2324.94,1655.93 2324.94,1667.1 2327.66,1669.82 2335.82,1669.82 2338.54,1667.1 2338.54,1655.93 2341.26,1653.21 2349.42,1653.21 2352.14,1655.93 2352.14,1667.1 2354.86,1669.82 2363.02,1669.82 2365.74,1667.1 2365.74,1650.77 2368.46,1648.05 2376.62,1648.05 2379.34,1650.77 2379.34,1665.33 2382.06,1668.05 2387.08,1668.05 2387.24,1667.9 2392,1663.13 2392,1642.53 2392,1640.73 2394.72,1638.01 2409.28,1638.01 2412,1635.29 2412,1627.13 2409.28,1624.41 2388.95,1624.41 2386.23,1621.69 2386.23,1613.53 2388.95,1610.81 2409.28,1610.81 2412,1608.09 2412,1599.93 2409.28,1597.21 2394.72,1597.21 2392,1594.49 2392,1583 2392,1569.39 2399.16,1562.23 2421.33,1562.23 2430.12,1571.02 2430.12,1647.32 2443.58,1660.77 2457.49,1660.77 2477,1641.27 2477,1582.37 2487.37,1572 2499.1,1572 2522.1,1595 2540.96,1595 2548.85,1587.11 2548.85,1564.16 2532.77,1548.09 2532.77,1538.73 2545,1526.5 2547.59,1526.5 2555.47,1526.5 2566,1526.5 2597,1526.5 2602.74,1532.24 2602.74,1622.09 2595.28,1629.56 2564.72,1629.56 2561.21,1629.56 2550.16,1629.56 2547.44,1632.28 2547.44,1640.44 2550.16,1643.16 2564.72,1643.16 2567.44,1645.88 2567.44,1652.69 2567.44,1662.98 2537.42,1693 2511,1693 2509.2,1693 2506.48,1690.28 2506.48,1677.27 2503.76,1674.55 2495.6,1674.55 2492.88,1677.27 2492.88,1702.35 2490.16,1705.07 2482,1705.07 2479.28,1702.35 2479.28,1677.27 2476.56,1674.55 2468.4,1674.55 2465.68,1677.27 2465.68,1702.35 2462.96,1705.07 2454.8,1705.07 2452.08,1702.35 2452.08,1695.72 2449.36,1693 2439.28,1693 2439.2,1693.07 2426.34,1693.07 2423.8,1690.54 2423.8,1670.7 v1(2423.95,1670.56)
  Bottom Layer w5.8: J3.105@2362.59,1651.36 2362.64,1651.3 2415.49,1651.3 2422.49,1658.3 2422.49,1669.09 v1(2423.95,1670.56)
PR0_PRU0_GPIO10: J3.109 U1.G18 | length 2006.4
  Top Layer w5.8: U1.G18@1324.6,1375.43 1344.25,1375.43 1360.04,1391.21 1360.04,1400.4 v1(1362.16,1402.52)
  L08_SIG2 w3.6: v1(1362.16,1402.52) 1363.79,1402.52 1390.29,1429.02 1511.49,1550.22 1511.49,1568.43 1532.08,1589.02 1586.18,1589.02 1611.11,1564.09 1611.11,1527.02 1621.68,1516.45 1648.3,1516.45 1653.92,1522.07 1689.13,1522.07 1700,1532.94 1700,1596.68 1712.93,1609.61 1751.33,1609.61 1757.95,1602.99 1814.76,1602.99 1932.38,1485.37 2023.72,1485.37 2063.72,1525.37 2151.58,1525.37 2172.23,1546.03 2172.23,1613.16 2201.91,1642.84 2346.58,1642.84 2375.43,1613.99 2375.43,1566.12 2417.35,1524.21 2421.89,1524.21 2429.13,1531.45 2439.38,1531.45 2450,1531.46 2469.73,1551.18 v1(2512.77,1551.18)
  Bottom Layer w5.8: J3.109@2362.59,1690.73 2416.35,1690.73 2458.02,1732.4 2488.76,1732.4 2507.35,1713.8 2507.35,1668.29 2517.85,1657.8 2517.85,1589.19 2509.29,1580.64 2509.29,1571.78 ; 2509.32,1571.76 2509.32,1565.78 2510.44,1564.66 2510.44,1553.52 v1(2512.77,1551.18)
PR0_PRU0_GPIO11: J3.114 R119.1 | length 3281.5
  L08_SIG2 w3.6: v1(1668.84,1425.97) 1668.84,1425.71 1713.88,1380.67 1780.67,1380.67 1799,1399 1839.25,1399 1877.23,1361.01 1911.17,1361.01 1930.07,1379.92 2332.58,1379.92 2333.21,1380.54 2348.61,1380.54 2351.33,1377.82 2351.33,1353.1 2354.05,1350.38 2362.21,1350.38 2364.93,1353.1 2364.93,1377.82 2367.65,1380.54 2375.81,1380.54 2378.53,1377.82 2378.53,1353.1 2381.25,1350.38 2389.41,1350.38 2392.13,1353.1 2392.13,1377.82 2394.85,1380.54 2403.01,1380.54 2405.73,1377.82 2405.73,1353.1 2408.45,1350.38 2416.61,1350.38 2419.33,1353.1 2419.33,1377.82 2422.05,1380.54 2430.21,1380.54 2432.93,1377.82 2432.93,1353.1 2435.65,1350.38 2443.81,1350.38 2446.53,1353.1 2446.53,1377.82 2449.25,1380.54 2457.41,1380.54 2460.13,1377.82 2460.13,1354.24 2462.85,1351.52 2471.01,1351.52 2473.73,1354.24 2473.73,1377.7 2476.45,1380.42 2480.29,1380.42 2483.94,1376.77 2488.52,1372.19 2488.52,1343.58 2483.94,1339 2372,1339 2366.69,1333.69 2366.69,1321.07 2373.08,1314.67 2395.65,1314.67 2411.72,1298.6 2593.5,1298.6 2673.4,1218.7 2757.16,1218.7 2839.3,1300.85 2839.3,1509.44 2816.7,1532.05 2816.7,1662.63 2798.47,1680.86 2798.47,1699.89 2794.8,1703.56 2794.8,1719.13 v1(2794.17,1719.76)
  Bottom Layer w5.8: R119.1@1333.66,1202.2 1334.45,1202.2 1346.99,1214.74 1352.3,1214.74 1388.73,1251.17 1436.26,1251.17 1455.04,1269.95 1455.04,1377.3 1498.83,1421.09 1498.83,1582.62 1510.23,1594.01 1589.47,1594.01 1615.36,1568.13 1615.36,1520.31 1641.24,1494.43 1641.24,1453.31 1668.58,1425.97 v1(1668.84,1425.97) ; J3.114@2588.19,1730.1 2783.83,1730.1 v1(2794.17,1719.76)
PR0_PRU0_GPIO12: J3.116 R121.1 | length 3220.7
  L08_SIG2 w3.6: v1(1669.36,1451.03) 1647.27,1451.03 1643,1446.76 1643,1419 1638.3,1414.3 1635.15,1414.3 1625.2,1424.25 1625.2,1469.21 1634.99,1479 1652,1479 1663,1468 1679,1468 1696,1451 1696,1423.86 1709.25,1410.61 1724.74,1410.61 1726.96,1412.84 1726.96,1454.63 1721.94,1459.65 1721.94,1469.5 1735.87,1483.44 1747.78,1483.44 1765.5,1465.72 1781.1,1465.72 1787.41,1472.02 1787.41,1491.26 1792.11,1495.96 1803.04,1495.96 1846.3,1452.69 1858.45,1452.69 1879.99,1431.15 1898.28,1431.15 1919.18,1410.24 1921.39,1410.24 1923.19,1410.24 1925.51,1412.56 1925.51,1427.92 1927.83,1430.24 1934.79,1430.24 1937.11,1427.92 1937.11,1411.36 1939.43,1409.04 1946.39,1409.04 1948.71,1411.36 1948.71,1427.92 1951.03,1430.24 1957.99,1430.24 1960.31,1427.92 1960.31,1411.36 1962.63,1409.04 1969.59,1409.04 1971.91,1411.36 1971.91,1427.92 1974.23,1430.24 1981.19,1430.24 1983.51,1427.92 1983.51,1411.36 1985.83,1409.04 1992.79,1409.04 1995.11,1411.36 1995.11,1427.92 1997.43,1430.24 2004.39,1430.24 2006.71,1427.92 2006.71,1412.56 2009.03,1410.24 2021,1410.24 2116.36,1410.24 2121.37,1415.25 2139.24,1415.25 2163.16,1391.34 2461.88,1391.34 2461.99,1391.23 2484.76,1391.23 2532.34,1343.65 2575.6,1343.65 2680.39,1238.86 2750.16,1238.86 2804.88,1293.58 2804.88,1351.32 2829.7,1376.14 2829.7,1505.46 2807.1,1528.07 2807.1,1658.65 2788.87,1676.88 2788.87,1692.71 2772.28,1709.3 2772.28,1747.18 v1(2788.89,1763.79)
  Bottom Layer w5.8: R121.1@1336.79,1238.42 1354.72,1238.42 1380.47,1264.17 1430.88,1264.17 1442.04,1275.33 1442.04,1382.69 1486.64,1427.28 1486.64,1589.43 1515.99,1618.78 1583.09,1618.78 1628.61,1573.26 1628.61,1525.44 1668.84,1485.22 1668.84,1451.56 v1(1669.36,1451.03) ; J3.116@2588.33,1749.65 2640.15,1749.65 2645.96,1743.83 2768.93,1743.83 v1(2788.89,1763.79)
PR0_PRU0_GPIO13: J3.118 R122.1 | length 3130.8
  Top Layer w5.8: R122.1@1516.86,1400.85 1531.89,1400.85 1535.85,1396.9 v1(1539.15,1396.9)
  L08_SIG2 w3.6: v1(1539.15,1396.9) 1539.15,1396.07 1552.56,1382.67 1625.11,1382.67 1641.49,1399.05 1678.95,1399.05 1723.78,1354.23 1725.05,1352.95 1728.9,1352.95 1739.19,1363.25 1743.04,1363.25 1748.81,1357.48 1748.81,1353.63 1736,1340.83 1736,1336.98 1741.77,1331.21 1745.62,1331.21 1758.42,1344.01 1762.27,1344.01 1768.04,1338.24 1768.04,1334.4 1755.24,1321.59 1755.24,1317.75 1761.01,1311.98 1764.85,1311.98 1777.66,1324.78 1781.5,1324.78 1787.27,1319.01 1787.27,1315.16 1776.98,1304.87 1776.98,1301.02 1781.73,1296.27 1783,1295 1788.27,1289.73 1795.49,1289.73 1807,1301.24 1807,1369.55 1817.46,1380 1837.55,1380 1848,1369.55 1848,1295.1 1853.37,1289.73 1863.36,1289.73 1865.16,1289.73 1867.88,1292.45 1867.88,1317.47 1870.6,1320.19 1878.76,1320.19 1881.48,1317.47 1881.48,1292.45 1884.2,1289.73 1892.36,1289.73 1895.08,1292.45 1895.08,1317.47 1897.8,1320.19 1905.96,1320.19 1908.68,1317.47 1908.68,1292.45 1911.4,1289.73 1919.56,1289.73 1922.28,1292.45 1922.28,1297.12 1925,1299.84 1933.16,1299.84 1935.88,1297.12 1935.88,1292.45 1938.6,1289.73 1950.7,1289.73 1957.26,1289.73 1976,1308.46 1976,1347.32 1996.68,1368.01 2010.36,1368.01 2025.76,1368.01 2028.48,1365.29 2028.48,1350.73 2031.2,1348.01 2039.36,1348.01 2042.08,1350.73 2042.08,1365.29 2044.8,1368.01 2052.96,1368.01 2055.68,1365.29 2055.68,1350.73 2058.4,1348.01 2066.56,1348.01 2069.28,1350.73 2069.28,1365.29 2072,1368.01 2078,1368.01 2187.04,1368.01 2200.44,1368.01 2202.76,1365.69 2202.76,1348.63 2205.08,1346.31 2212.04,1346.31 2214.36,1348.63 2214.36,1368 2216.68,1370.32 2223.64,1370.32 2225.96,1368 2225.96,1327.2 2228.28,1324.88 2235.24,1324.88 2237.56,1327.2 2237.56,1368 2239.88,1370.32 2246.84,1370.32 2249.16,1368 2249.16,1330.49 2251.48,1328.17 2258.44,1328.17 2260.76,1330.49 2260.76,1365.69 2263.08,1368.01 2286.34,1368.01 2303.35,1368.01 2366.28,1305.07 2389.97,1305.07 2407.25,1287.8 2590.72,1287.8 2670.62,1207.9 2759.94,1207.9 2848.9,1296.87 2848.9,1514.95 2826.3,1537.55 2826.3,1666.61 2810.97,1681.93 2810.97,1765.47 2785.01,1791.43 2738.29,1791.43 2712.98,1816.75 2701.82,1816.75 2696.2,1811.13 2696.2,1801.8 2739,1759 2758,1759 2761.39,1762.39 v1(2761.39,1774.63)
  Bottom Layer w5.8: J3.118@2588.19,1769.47 2588.24,1769.42 2638.87,1769.42 2651.46,1756.83 2711.32,1756.83 2729.12,1774.63 v1(2761.39,1774.63)
PR0_PRU0_GPIO14: J3.120 R124.1 | length 2996.2
  L08_SIG2 w3.6: v1(1504.62,1376.91) 1507.38,1379.66 1512.91,1379.66 1513.93,1380.68 1534.27,1380.68 1542.27,1372.69 1631.38,1372.69 1666.9,1337.17 1720.54,1337.17 1778.78,1278.93 1977.93,1278.93 1993.98,1294.98 2010.68,1294.98 2026.08,1294.98 2028.8,1292.26 2028.8,1283.65 2031.52,1280.93 2039.68,1280.93 2042.4,1283.65 2042.4,1296.73 2045.12,1299.45 2053.28,1299.45 2056,1296.73 2056,1283.65 2058.72,1280.93 2066.88,1280.93 2069.6,1283.65 2069.6,1303.46 2072.32,1306.18 2080.48,1306.18 2083.2,1303.46 2083.2,1283.65 2085.92,1280.93 2094.08,1280.93 2096.8,1283.65 2096.8,1312.26 2099.52,1314.98 2107.68,1314.98 2110.4,1312.26 2110.4,1274.76 2113.12,1272.04 2121.28,1272.04 2124,1274.76 2124,1292.26 2126.72,1294.98 2134.67,1294.98 2147.74,1294.98 2149.54,1294.98 2151.86,1297.3 2151.86,1326.43 2154.18,1328.75 2161.14,1328.75 2163.46,1326.43 2163.46,1295.58 2165.78,1293.26 2172.74,1293.26 2175.06,1295.58 2175.06,1315.01 2177.38,1317.33 2184.34,1317.33 2186.66,1315.01 2186.66,1295.51 2188.98,1293.19 2195.94,1293.19 2198.26,1295.51 2198.26,1310.39 2200.58,1312.71 2207.54,1312.71 2209.86,1310.39 2209.86,1296.96 2212.18,1294.64 2219.14,1294.64 2221.46,1296.96 2221.46,1304.45 2223.78,1306.77 2230.74,1306.77 2233.06,1304.45 2233.06,1297.3 2235.38,1294.98 2262.23,1294.98 2384.79,1294.98 2402.77,1277 2587.71,1277 2667.61,1197.1 2762.71,1197.1 2859.9,1294.29 2859.9,1603.59 2863.55,1607.24 2863.55,1622.22 2841.47,1644.3 2841.47,1666.84 2820.57,1687.74 2820.57,1759.58 2832.47,1771.48 2832.47,1794.76 2817.63,1809.6 2781.82,1809.6 2781.44,1809.21 2767.52,1809.21 2740.9,1835.83 2740.9,1850.24 2718.83,1872.31 2706.01,1872.31 2695.32,1861.62 2695.32,1848.3 2741.22,1802.4 2800.07,1802.4 2814.27,1788.2 v1(2817.32,1788.2)
  Bottom Layer w5.8: v1(1504.62,1376.91) 1504.62,1373.61 1508.37,1369.86 R124.1@1508.37,1313.15 ; J3.120@2588.19,1789.15 2641.89,1789.15 2652.44,1799.71 2687.21,1799.71 2694.72,1792.19 2751.4,1792.19 2758.03,1798.82 2806.7,1798.82 v1(2817.32,1788.2)
PR0_PRU0_GPIO15: J3.115 U1.L16 | length 3357.6
  Top Layer w5.8: U1.L16@1261.61,1249.45 v1(1277.35,1233.7)
  L08_SIG2 w3.6: v1@1276.88,1234.77 1280.71,1230.94 1290.18,1230.94 1296.58,1224.55 1375.16,1224.55 1384.13,1215.57 1384.13,1199.31 1390.29,1193.15 1472.94,1110.5 1480.34,1110.5 1487.73,1103.11 1558.38,1103.11 1677.4,984.08 2684,984.08 2980.12,1280.21 2980.12,1464.67 2972.33,1472.45 2972.33,1676.74 2950.21,1698.86 2950.21,1784.72 2843.58,1891.35 v1(2800.28,1891.35)
  Bottom Layer w5.8: J3.115@2362.59,1749.78 2418.78,1749.78 2448.17,1779.17 2448.17,1880.33 2515.02,1947.18 2596.07,1947.18 2626,1917.25 2626,1870.94 2656.86,1840.08 2701.99,1840.08 2710.87,1831.19 2720.13,1831.19 2737.27,1848.33 2737.27,1859.02 2769.59,1891.35 v1(2800.28,1891.35)
PR0_PRU0_GPIO16: J3.112 R126.1 | length 3241.8
  Top Layer w5.8: R126.1@1383.54,1347.19 1383.54,1379.93 1398.92,1395.31 1459.03,1395.31 1468.68,1385.65 ; 1468.73,1385.65 1479.27,1375.12 1479.27,1369.48 v1(1481.6,1367.15)
  L08_SIG2 w3.6: v1(1481.6,1367.15) 1483.65,1367.15 1490.7,1360.1 1507.03,1360.1 1520.05,1347.08 1530.56,1347.08 1546.84,1330.8 1546.84,1313.4 1557.76,1302.47 1583.53,1302.47 1590.05,1295.95 1591.32,1294.68 1595.17,1294.68 1623.97,1323.48 1627.82,1323.48 1633.59,1317.71 1633.59,1313.87 1603.81,1284.09 1603.81,1280.24 1609.58,1274.47 1613.43,1274.47 1643.21,1304.25 1647.05,1304.25 1652.82,1298.48 1652.82,1294.63 1624.76,1266.57 1624.76,1262.72 1627.47,1260 1632,1260 1646.73,1260 1648.53,1260 1651.25,1262.72 1651.25,1277.28 1653.97,1280 1662.13,1280 1664.85,1277.28 1664.85,1262.72 1667.57,1260 1675,1260 1688.4,1260 1709.03,1239.37 2139.1,1239.37 2140.91,1239.37 2143.63,1242.09 2143.63,1256.86 2146.35,1259.58 2154.51,1259.58 2157.23,1256.86 2157.23,1242.09 2159.95,1239.37 2168.11,1239.37 2170.83,1242.09 2170.83,1268.11 2173.55,1270.83 2181.71,1270.83 2184.43,1268.11 2184.43,1242.09 2187.15,1239.37 2195.31,1239.37 2198.03,1242.09 2198.03,1268.11 2200.75,1270.83 2208.91,1270.83 2211.63,1268.11 2211.63,1242.09 2214.35,1239.37 2222.51,1239.37 2225.23,1242.09 2225.23,1268.11 2227.95,1270.83 2236.11,1270.83 2238.83,1268.11 2238.83,1242.09 2241.55,1239.37 2249.71,1239.37 2252.43,1242.09 2252.43,1268.11 2255.15,1270.83 2263.31,1270.83 2266.03,1268.11 2266.03,1242.09 2268.75,1239.37 2276.91,1239.37 2279.63,1242.09 2279.63,1245.31 2282.35,1248.03 2290.51,1248.03 2293.23,1245.31 2293.23,1242.09 2294.59,1240.73 2304.5,1240.73 2319.17,1255.4 2327.33,1255.4 2329.13,1255.4 2331.85,1258.12 2331.85,1268.11 2334.57,1270.83 2342.73,1270.83 2345.45,1268.11 2345.45,1242.09 2348.17,1239.37 2356.33,1239.37 2359.05,1242.09 2359.05,1268.11 2361.77,1270.83 2369.93,1270.83 2372.65,1268.11 2372.65,1258.12 2375.37,1255.4 2387.33,1255.4 2445.37,1255.4 2471.92,1228.85 2489.46,1228.85 2491.26,1228.85 2493.98,1231.57 2493.98,1248.96 2496.7,1251.68 2504.86,1251.68 2507.58,1248.96 2507.58,1230.29 2510.3,1227.57 2518.46,1227.57 2521.18,1230.29 2521.18,1248.96 2523.9,1251.68 2532.06,1251.68 2534.78,1248.96 2534.78,1230.29 2537.5,1227.57 2545.66,1227.57 2548.38,1230.29 2548.38,1248.96 2551.1,1251.68 2559.26,1251.68 2561.98,1248.96 2561.98,1230.29 2564.7,1227.57 2572.86,1227.57 2575.58,1230.29 2575.58,1243.96 2578.3,1246.68 2586.46,1246.68 2589.18,1243.96 2589.18,1231.57 2591.9,1228.85 2599.23,1228.85 2604.15,1228.85 2657.5,1175.5 2768.26,1175.5 2879.1,1286.33 2879.1,1595.64 2882.75,1599.28 2882.75,1630.18 2873.77,1639.15 2873.77,1685.63 2864.39,1695.01 2864.39,1733.94 2838.02,1760.31 2834.87,1760.31 2830.17,1755.61 2830.17,1714.98 2832.28,1712.87 2847.3,1712.87 v1(2847.56,1712.61)
  Bottom Layer w5.8: J3.112@2588.19,1710.41 2755.36,1710.41 2764.46,1701.31 2812.68,1701.31 2823.98,1712.61 v1(2847.56,1712.61)
PR0_PRU1_GPIO0: J3.78 R149.1 | length 1330.6
  L08_SIG2 w3.6: v1(2026.12,1819.59) 2027.06,1820.53 2027.06,1831.81 2064.68,1869.42 2228.48,1869.42 2303.92,1793.98 2387.25,1793.98 2401.48,1779.75 2613.51,1779.75 2754.98,1638.29 2754.98,1592 2754.3,1591.32 2754.3,1540.53 2773.17,1521.66 2773.17,1451.09 2754.32,1432.24 2754.32,1386.28 2744.36,1376.32 v1(2744.36,1372.86)
  Bottom Layer w5.8: v1(2026.12,1819.59) 2027.85,1817.86 2027.85,1795.94 R149.1@2029.58,1794.21 ; J3.78@2588.19,1375.77 2642.41,1375.77 2656.31,1361.86 2686.42,1361.86 2695.18,1370.62 2742.12,1370.62 v1(2744.36,1372.86)
PR0_PRU1_GPIO1: J3.80 R150.1 | length 1153.9
  L08_SIG2 w3.6: v1(2148.73,1848.79) 2182.22,1815.29 2253.9,1815.29 2299.04,1770.15 2407.27,1770.15 ; 2407.34,1770.09 2420.74,1770.09 2423.06,1767.77 2423.06,1763.43 2425.38,1761.11 2432.34,1761.11 2434.66,1763.43 2434.66,1767.77 2436.98,1770.09 2443.94,1770.09 2446.26,1767.77 2446.26,1763.87 2448.58,1761.55 2455.54,1761.55 2457.86,1763.87 2457.86,1767.77 2460.18,1770.09 2540.83,1770.09 2603.05,1770.09 2745.38,1627.76 2745.38,1595.98 2744.7,1595.3 2744.7,1536.56 2763.57,1517.69 2763.57,1455.07 2737.52,1429.01 v1(2737.52,1406.25)
  Bottom Layer w5.8: R150.1@2120.42,1847.43 2121.1,1848.11 2148.05,1848.11 v1(2148.73,1848.79) ; J3.80@2588.19,1395.45 2643.86,1395.45 2655.69,1383.62 2729.8,1383.62 2737.52,1391.34 v1(2737.52,1406.25)
PR0_PRU1_GPIO2: J3.82 R151.1 | length 1142.5
  Top Layer w5.8: v1(2712.46,1401.52) 2712.46,1400.93 2690.74,1379.21 2690.74,1352.66 2701.51,1341.89 2717.22,1341.89 2725.04,1349.71 2737.81,1349.71 2749.4,1338.12 2749.4,1292.04 2763.59,1277.84 2787.84,1277.84 2804.6,1294.6 2804.6,1350.61 2816.64,1362.65 2816.64,1408.12 2801.73,1423.03 R151.1@2769.4,1423.03
  Bottom Layer w5.8: J3.82@2588.19,1415.14 2645.2,1415.14 2654.74,1405.6 2676.66,1405.6 2705.33,1434.27 2705.33,1478.6 2735.06,1508.32 2881.41,1508.32 2923.69,1466.04 2923.69,1455.74 2918.85,1450.9 2900.13,1450.9 2868.03,1483 2740.36,1483 2721.01,1463.64 2721.01,1430.36 2712.46,1421.82 v1(2712.46,1401.52)
PR0_PRU1_GPIO3: J3.84 R152.1 | length 1104.7
  L08_SIG2 w3.6: v1(2148,1764.63) 2157.5,1774.13 2172.51,1774.13 2216.62,1730.02 2230.74,1730.02 2232.54,1730.02 2234.86,1732.34 2234.86,1747.7 2237.18,1750.02 2244.14,1750.02 2246.46,1747.7 2246.46,1730.67 2248.78,1728.35 2255.74,1728.35 2258.06,1730.67 2258.06,1745.68 2260.38,1748 2267.34,1748 2269.66,1745.68 2269.66,1730.67 2271.98,1728.35 2278.94,1728.35 2281.26,1730.67 2281.26,1745.68 2283.58,1748 2290.54,1748 2292.86,1745.68 2292.86,1732.34 2295.18,1730.02 2301.23,1730.02 2382.72,1730.02 2393.99,1741.29 2602.73,1741.29 2726.18,1617.85 2726.18,1603.93 2725.5,1603.25 2725.5,1528.21 2729.83,1523.88 2729.83,1494.95 2703.29,1468.4 2703.29,1441.92 2688.27,1426.91 v1(2667.78,1426.91)
  Bottom Layer w5.8: R152.1@2117.55,1770.34 2138.99,1770.34 2144.7,1764.63 v1(2148,1764.63) ; J3.84@2588.43,1435.07 2642.58,1435.07 2650.74,1426.91 v1(2667.78,1426.91)
PR0_PRU1_GPIO4: J3.93 R153.1 | length 1611.7
  Bottom Layer w5.8: R153.1@2169.4,2144.63 2213,2144.63 2232.43,2164.07 2232.43,2183.48 2217.57,2198.35 2200.25,2198.35 2179.35,2219.25 2179.35,2265.62 2193.4,2279.66 2254.38,2279.66 2272.1,2261.94 2272.1,2175.67 2196,2099.57 2196,2073 2164.77,2041.77 2164.77,2014.86 2188.32,1991.32 2194.59,1991.32 2210.18,1991.3 2246.25,1955.23 2246.25,1902.77 2256.02,1893 2400,1893 2414,1879 2414,1841 2408.81,1835.81 2393.19,1835.81 2387.99,1841.02 2387.99,1856.02 2366,1878 2263.12,1878 2246.25,1861.13 2246.25,1846.77 2223.33,1823.85 2223.33,1778.4 2269.6,1732.13 2269.6,1562.94 2299.29,1533.25 J3.93@2362.59,1533.25
PR0_PRU1_GPIO5: J3.95 R154.1 | length 973.4
  Bottom Layer w5.8: R154.1@2207.4,2010.55 2223.98,2010.55 2226.85,2007.68 2226.85,1996.56 2259.25,1964.16 2259.25,1928 2280.41,1906.85 2415.31,1906.85 2433.23,1888.93 2433.23,1827.22 2415.65,1809.64 2385.36,1809.64 2371.26,1823.74 2371.26,1850.83 2359.32,1862.77 2286.87,1862.77 2240.76,1816.67 2240.76,1779.35 2282.6,1737.52 2282.6,1569.96 2299.63,1552.93 J3.95@2362.59,1552.93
